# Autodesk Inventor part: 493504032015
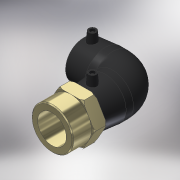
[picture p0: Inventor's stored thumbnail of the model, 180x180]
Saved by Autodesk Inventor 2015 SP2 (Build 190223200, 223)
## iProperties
Created: 2017-06
Part Number: 493504032015
Material: Generic
Description: PLASSON 90° ELBOW FEMALE TRANSITION 32-1.1/2''
Document SubType Name: Modeling
Designer: KIM
Mass: 136.169 g
Surface Area: 429.711 cm^2
Volume: 136.169 cm^3
Density: 1 g/cm^3
Appearance: Rubber - Black
Author: KIM
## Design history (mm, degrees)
derived "493504.ipt"
feature "Solid1::493504.ipt"
tag "TaggingFeature1"
body "Solid1"
other parameters: "d2" = 44, "d4" = 27.66667, "d5" = 39.6, "d8" = 168 deg, "d10" = 16, "d11" = 5.33333, "d29" = 43, "d30" = 15, "d31" = 45.65, "d34" = 5 deg, "d41" = 4, "d42" = 14, "d43" = 0, "d48" = 61, "d49" = 32, "d50" = 27.2, "d51" = 16, "d54" = 90 deg, "d57" = 32, "d59" = 0, "d61" = 90 deg, "d86" = 3, "d87" = 0, "d93" = 0.1, "d96" = 44.845, "d97" = 23, "d98" = 25, "d99" = 57.2, "d108" = 0, "d109" = 0.96, "d112" = 45 deg, "d113" = 45 deg, "d114" = 1.6, "d_" = 32, "L_" = 108, "D_" = 23, "A_" = 43, "d_2" = 12, "L_2" = 25, "D_1" = 44, "Rp_" = 44.845
